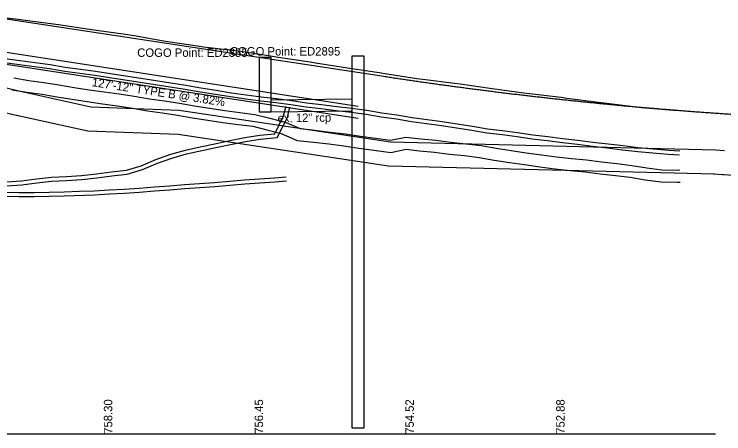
# Model space of a CAD drawing. Extents: x 1833473 to 1837132, y 704683 to 706683.
# Drawn here: x 1834678.2 to 1834913.6, y 705682.6 to 705821.9 of the extents above; entities that cross this region are included whole.
import ezdxf

# ---------------------------------------------------------------- set-up
doc = ezdxf.new("R2010")
doc.units = 0
for name, color, linetype in [('DR_P_Storm_Sewer', 7, 'Continuous'), ('DR_P_Text', 7, 'Continuous'), ('DR_X_Storm_Sewer', 7, 'Continuous'), ('DR_X_Text', 7, 'Continuous'), ('GK_Cells', 7, 'Continuous'), ('PF_P_Grade_Line', 7, 'Continuous'), ('PF_X_Ground_Line', 7, 'Continuous'), ('PF_X_Text', 7, 'Continuous'), ('SC_Scratch1', 7, 'Continuous'), ('UT_X_Electric', 7, 'Continuous'), ('UT_X_Sanitary_Line', 7, 'Continuous'), ('UT_X_Telecom', 7, 'Continuous'), ('UT_X_Water', 7, 'Continuous')]:
    doc.layers.add(name, color=color, linetype=linetype)

msp = doc.modelspace()

# ---------------------------------------------------------------- linework, layer by layer
at = {"layer": 'DR_P_Storm_Sewer'}
for p, q in [((1834665.78, 705810.77), (1834792.35, 705791.41)), ((1834665.78, 705806.77), (1834792.35, 705787.41))]:
    msp.add_line(p, q, dxfattribs=at)
at = {"layer": 'DR_X_Storm_Sewer'}
for p, q in [((1834763.48, 705793.53), (1834790.26, 705793.85)), ((1834763.48, 705789.53), (1834790.26, 705789.85))]:
    msp.add_line(p, q, dxfattribs=at)
msp.add_lwpolyline([(1834761.48, 705807.53), (1834759.48, 705807.53), (1834759.48, 705789.53), (1834763.48, 705789.53), (1834763.48, 705807.53), (1834761.48, 705807.53)], dxfattribs=at)
at = {"layer": 'GK_Cells'}
msp.add_line((1833710.78, 705682.65), (1834910.78, 705682.65), dxfattribs=at)
msp.add_line((1833710.78, 705682.65), (1834910.78, 705682.65), dxfattribs=at)
at = {"layer": 'PF_P_Grade_Line'}
msp.add_line((1834665.78, 705821.9), (1834800.78, 705801.3), dxfattribs=at)
msp.add_spline([(1834800.78, 705801.3), (1834802.58, 705801.03), (1834804.38, 705800.76), (1834806.18, 705800.49), (1834807.98, 705800.22), (1834809.78, 705799.96), (1834811.58, 705799.7), (1834813.38, 705799.44), (1834815.18, 705799.18), (1834816.98, 705798.93), (1834818.78, 705798.68), (1834820.58, 705798.43), (1834822.38, 705798.18), (1834824.18, 705797.94), (1834825.98, 705797.7), (1834827.78, 705797.46), (1834829.58, 705797.22), (1834831.38, 705796.99), (1834833.18, 705796.75), (1834834.98, 705796.53), (1834836.78, 705796.3), (1834838.58, 705796.07), (1834840.38, 705795.85), (1834842.18, 705795.63), (1834843.98, 705795.41), (1834845.78, 705795.2), (1834847.58, 705794.99), (1834849.38, 705794.78), (1834851.18, 705794.57), (1834852.98, 705794.37), (1834854.78, 705794.16), (1834856.58, 705793.96), (1834858.38, 705793.76), (1834860.18, 705793.57), (1834861.98, 705793.38), (1834863.78, 705793.19), (1834865.58, 705793), (1834867.38, 705792.81), (1834869.18, 705792.63), (1834870.98, 705792.45), (1834872.78, 705792.27), (1834874.58, 705792.1), (1834876.38, 705791.92), (1834878.18, 705791.75), (1834879.98, 705791.58), (1834881.78, 705791.42), (1834883.58, 705791.25), (1834885.38, 705791.09), (1834887.18, 705790.93), (1834888.98, 705790.78), (1834890.78, 705790.63), (1834892.58, 705790.47), (1834894.38, 705790.33), (1834896.18, 705790.18), (1834897.98, 705790.03), (1834899.78, 705789.89), (1834901.58, 705789.75), (1834903.38, 705789.62), (1834905.18, 705789.48), (1834906.98, 705789.35), (1834908.78, 705789.22), (1834910.58, 705789.1), (1834912.38, 705788.97), (1834914.18, 705788.85), (1834915.98, 705788.73), (1834917.78, 705788.61), (1834919.58, 705788.5), (1834921.38, 705788.39), (1834923.18, 705788.28), (1834924.98, 705788.17), (1834926.78, 705788.07), (1834928.58, 705787.96), (1834930.38, 705787.86), (1834932.18, 705787.77), (1834933.98, 705787.67), (1834935.78, 705787.58), (1834937.58, 705787.49), (1834939.38, 705787.4), (1834941.18, 705787.32), (1834942.98, 705787.23), (1834944.78, 705787.15), (1834946.58, 705787.07), (1834948.38, 705787), (1834950.18, 705786.93), (1834951.98, 705786.86), (1834953.78, 705786.79), (1834955.58, 705786.72), (1834957.38, 705786.66), (1834959.18, 705786.6), (1834960.98, 705786.54), (1834962.78, 705786.48), (1834964.58, 705786.43), (1834966.38, 705786.38), (1834968.18, 705786.33), (1834969.98, 705786.29), (1834971.78, 705786.24), (1834973.58, 705786.2), (1834975.38, 705786.16), (1834977.18, 705786.13), (1834978.98, 705786.09), (1834980.78, 705786.06)], degree=3, dxfattribs=at)
at = {"layer": 'PF_X_Ground_Line'}
msp.add_lwpolyline([(1834670.23, 705821.4), (1834680.37, 705820.12), (1834682.75, 705819.79), (1834692.95, 705818.46), (1834703.27, 705816.9), (1834705.5, 705816.57), (1834715.89, 705815.13), (1834718.02, 705814.84), (1834728.44, 705812.98), (1834738.99, 705811.44), (1834740.98, 705811.1), (1834751.54, 705809.87), (1834753.36, 705809.65), (1834763.92, 705807.92), (1834765.79, 705807.66), (1834776.37, 705806.08), (1834778.22, 705805.75), (1834788.78, 705804.12), (1834799.33, 705802.52), (1834801.21, 705802.25), (1834811.75, 705800.57), (1834813.73, 705800.31), (1834824.3, 705799.05), (1834826.19, 705798.77), (1834836.73, 705797.29), (1834847.26, 705795.75), (1834849.11, 705795.53), (1834859.64, 705794.31), (1834861.51, 705794.06), (1834872.06, 705792.7), (1834873.95, 705792.49), (1834884.49, 705791.19), (1834886.33, 705790.98), (1834896.9, 705790.06), (1834898.97, 705789.93)], dxfattribs=at)
at = {"layer": 'UT_X_Electric'}
for p, q in [((1834732.91, 705790.07), (1834803.08, 705779.54)), ((1834732.62, 705782.08), (1834802.41, 705771.55)), ((1834803.08, 705779.54), (1834910.78, 705776.93)), ((1834910.78, 705776.93), (1834913.75, 705776.69)), ((1834802.37, 705771.55), (1834910.58, 705768.93)), ((1834910.15, 705768.95), (1834913.12, 705768.72)), ((1834913.57, 705768.69), (1834918.57, 705768.41))]:
    msp.add_line(p, q, dxfattribs=at)
for points in [[(1834585.78, 705806.89), (1834638.05, 705806.44), (1834681.25, 705796.1)], [(1834585.5, 705798.89), (1834637.07, 705798.45), (1834679.39, 705788.32)], [(1834680.78, 705796.24), (1834703.7, 705791.14), (1834732.91, 705790.07)], [(1834675.65, 705766.3), (1834680.62, 705766.58), (1834685.6, 705767.24), (1834690.57, 705767.78), (1834695.55, 705768), (1834700.52, 705768.36), (1834705.49, 705768.92), (1834710.47, 705769.54), (1834715.44, 705770.13), (1834720.37, 705771.58), (1834725.27, 705773.69), (1834730.16, 705775.4), (1834735.05, 705776.82), (1834739.94, 705777.86), (1834744.83, 705778.91), (1834749.76, 705779.93), (1834754.72, 705780.93), (1834759.68, 705781.71), (1834764.64, 705782.24), (1834767.58, 705788.12), (1834768.39, 705791.35)], [(1834675.74, 705764.97), (1834680.75, 705765.26), (1834685.76, 705765.91), (1834690.67, 705766.45), (1834695.62, 705766.66), (1834700.64, 705767.03), (1834705.65, 705767.59), (1834710.63, 705768.22), (1834715.71, 705768.82), (1834720.83, 705770.32), (1834725.75, 705772.45), (1834730.56, 705774.13), (1834735.37, 705775.52), (1834745.1, 705777.61), (1834750.03, 705778.62), (1834754.96, 705779.62), (1834759.85, 705780.39), (1834765.5, 705780.99), (1834768.84, 705787.65), (1834769.68, 705791.03)], [(1834679.04, 705788.43), (1834702.68, 705783.17), (1834732.62, 705782.08)], [(1834674.84, 705762.81), (1834679.83, 705762.78), (1834684.82, 705762.74), (1834689.8, 705762.84), (1834694.79, 705762.98), (1834699.78, 705763.16), (1834704.77, 705763.33), (1834709.76, 705763.57), (1834714.75, 705763.85), (1834719.74, 705764.19), (1834724.73, 705764.58), (1834729.72, 705764.97), (1834734.71, 705765.37), (1834739.71, 705765.72), (1834744.7, 705766.07), (1834749.68, 705766.45), (1834754.65, 705766.9), (1834759.61, 705767.3), (1834764.57, 705767.63), (1834768.39, 705767.95)], [(1834674.99, 705761.47), (1834679.82, 705761.45), (1834684.82, 705761.4), (1834689.84, 705761.51), (1834694.84, 705761.65), (1834704.83, 705762), (1834709.83, 705762.24), (1834714.83, 705762.52), (1834719.83, 705762.86), (1834724.83, 705763.25), (1834729.83, 705763.64), (1834734.81, 705764.04), (1834739.8, 705764.39), (1834744.8, 705764.74), (1834749.79, 705765.13), (1834754.76, 705765.58), (1834759.7, 705765.97), (1834764.67, 705766.3), (1834768.5, 705766.62)]]:
    msp.add_lwpolyline(points, dxfattribs=at)
msp.add_arc((1834914.68, 705788.66), 20, 265.5309, 266.8232, dxfattribs=at)
at = {"layer": 'UT_X_Sanitary_Line'}
msp.add_lwpolyline([(1834792.26, 705807.97), (1834790.26, 705807.97), (1834790.26, 705684.61), (1834794.26, 705684.61), (1834794.26, 705807.97), (1834792.26, 705807.97)], dxfattribs=at)
at = {"layer": 'UT_X_Telecom'}
for points in [[(1834675.19, 705807.15), (1834680.19, 705806.49), (1834685.19, 705805.82), (1834690.19, 705805.15), (1834695.19, 705804.33), (1834700.19, 705803.61), (1834705.19, 705802.95), (1834710.19, 705802.25), (1834715.19, 705801.44), (1834720.19, 705800.66), (1834725.19, 705799.9), (1834730.19, 705799.16), (1834735.19, 705798.33), (1834740.19, 705797.46), (1834745.19, 705796.64), (1834750.19, 705795.85), (1834755.19, 705795.12), (1834760.19, 705794.49), (1834765.19, 705793.96), (1834770.19, 705793.23), (1834775.19, 705792.51), (1834780.19, 705791.94), (1834785.19, 705791.27), (1834790.19, 705790.75), (1834795.19, 705790.03), (1834800.19, 705789.18), (1834805.19, 705788.47), (1834810.19, 705787.65), (1834815.19, 705786.9), (1834820.19, 705786.24), (1834825.19, 705785.51), (1834830.19, 705784.71), (1834835.19, 705783.9), (1834840.19, 705783.27), (1834845.19, 705782.62), (1834850.19, 705781.87), (1834855.19, 705781.28), (1834860.19, 705780.7), (1834865.19, 705780.08), (1834870.19, 705779.44), (1834875.19, 705778.89), (1834880.19, 705778.27), (1834885.19, 705777.7), (1834890.19, 705777.19), (1834895.19, 705776.75), (1834898.97, 705776.53)], [(1834675.01, 705805.83), (1834680.01, 705805.16), (1834685.01, 705804.5), (1834689.99, 705803.83), (1834694.99, 705803.02), (1834700.01, 705802.29), (1834705.01, 705801.63), (1834709.99, 705800.93), (1834714.98, 705800.13), (1834719.99, 705799.34), (1834724.99, 705798.59), (1834729.98, 705797.84), (1834734.96, 705797.01), (1834739.97, 705796.14), (1834744.98, 705795.32), (1834749.99, 705794.53), (1834755.01, 705793.8), (1834760.03, 705793.17), (1834765.02, 705792.64), (1834770, 705791.91), (1834775.02, 705791.19), (1834780.02, 705790.62), (1834785.03, 705789.95), (1834790.02, 705789.43), (1834794.98, 705788.71), (1834799.98, 705787.86), (1834804.99, 705787.15), (1834809.98, 705786.34), (1834815, 705785.58), (1834820, 705784.92), (1834824.98, 705784.19), (1834829.97, 705783.39), (1834835, 705782.58), (1834840.02, 705781.95), (1834845, 705781.3), (1834850.01, 705780.55), (1834855.03, 705779.96), (1834860.03, 705779.37), (1834865.02, 705778.75), (1834870.03, 705778.12), (1834875.03, 705777.57), (1834880.03, 705776.94), (1834885.04, 705776.37), (1834890.06, 705775.86), (1834895.09, 705775.42), (1834898.89, 705775.2)]]:
    msp.add_lwpolyline(points, dxfattribs=at)
at = {"layer": 'UT_X_Water'}
for points in [[(1834678.08, 705800.74), (1834683.08, 705799.92), (1834688.08, 705799.27), (1834693.08, 705798.45), (1834698.08, 705797.62), (1834703.07, 705796.83), (1834708.07, 705796.14), (1834713.07, 705795.44), (1834718.07, 705794.64), (1834723.07, 705793.83), (1834728.07, 705793.09), (1834733.07, 705792.32), (1834738.07, 705791.48), (1834743.07, 705790.7), (1834748.07, 705789.95), (1834753.07, 705789.23), (1834758.07, 705788.66), (1834763.07, 705787.4), (1834768.07, 705786.12), (1834773.07, 705783.92), (1834778.07, 705783.42), (1834783.07, 705782.79), (1834788.07, 705782.14), (1834793.07, 705781.46), (1834798.07, 705780.79), (1834803.07, 705780.11), (1834808.07, 705781.11), (1834813.07, 705780.56), (1834818.07, 705780.05), (1834823.07, 705779.4), (1834828.07, 705778.93), (1834833.07, 705778.27), (1834838.07, 705777.46), (1834843.07, 705776.69), (1834848.07, 705775.93), (1834853.07, 705775.22), (1834858.07, 705774.6), (1834863.07, 705773.99), (1834868.07, 705773.55), (1834873.06, 705772.88), (1834878.06, 705772.35), (1834883.06, 705771.74), (1834888.06, 705770.89), (1834893.06, 705770.25), (1834898.06, 705770.17), (1834898.97, 705770.21)], [(1834677.47, 705796.78), (1834682.5, 705795.97), (1834687.49, 705795.31), (1834692.42, 705794.5), (1834697.43, 705793.67), (1834702.49, 705792.87), (1834707.52, 705792.18), (1834712.48, 705791.48), (1834717.44, 705790.69), (1834722.46, 705789.88), (1834727.48, 705789.14), (1834732.43, 705788.37), (1834737.43, 705787.53), (1834742.47, 705786.75), (1834747.49, 705786), (1834752.56, 705785.27), (1834757.35, 705784.72), (1834762.08, 705783.52), (1834766.76, 705782.33), (1834772.04, 705780), (1834777.62, 705779.45), (1834782.56, 705778.83), (1834787.54, 705778.17), (1834792.53, 705777.49), (1834797.53, 705776.82), (1834803.19, 705776.05), (1834808.25, 705777.06), (1834812.65, 705776.58), (1834817.6, 705776.08), (1834822.62, 705775.43), (1834827.62, 705774.96), (1834832.48, 705774.31), (1834837.44, 705773.51), (1834842.46, 705772.73), (1834847.48, 705771.97), (1834852.54, 705771.25), (1834857.58, 705770.63), (1834862.65, 705770.02), (1834867.62, 705769.57), (1834872.59, 705768.91), (1834877.61, 705768.38), (1834882.49, 705767.78), (1834887.48, 705766.93), (1834892.78, 705766.26), (1834898.11, 705766.17), (1834899.13, 705766.21)]]:
    msp.add_lwpolyline(points, dxfattribs=at)

# ---------------------------------------------------------------- texts
at = {"layer": 'DR_P_Text'}
msp.add_text('127\'-12" TYPE B @ 3.82%', height=2.8, rotation=351.3035, dxfattribs=at).set_placement((1834703.88, 705798.04))
at = {"layer": 'DR_X_Text'}
msp.add_text('ex. 12" rcp', height=2.8, rotation=0.6846, dxfattribs=at).set_placement((1834765.61, 705786.01))
at = {"layer": 'PF_X_Text'}
for s, p in [('758.30', (1834710.78, 705682.65)), ('756.45', (1834760.78, 705682.65)), ('754.52', (1834810.78, 705682.65)), ('752.88', (1834860.78, 705682.65))]:
    msp.add_text(s, height=2.8, rotation=90, dxfattribs=at).set_placement(p)
at = {"layer": 'SC_Scratch1'}
for s, p in [('COGO Point: ED2855', (1834719.04, 705807.74)), ('COGO Point: ED2895', (1834749.77, 705808.18))]:
    msp.add_text(s, height=2.8, dxfattribs=at).set_placement(p)

doc.saveas('drawing.dxf')
